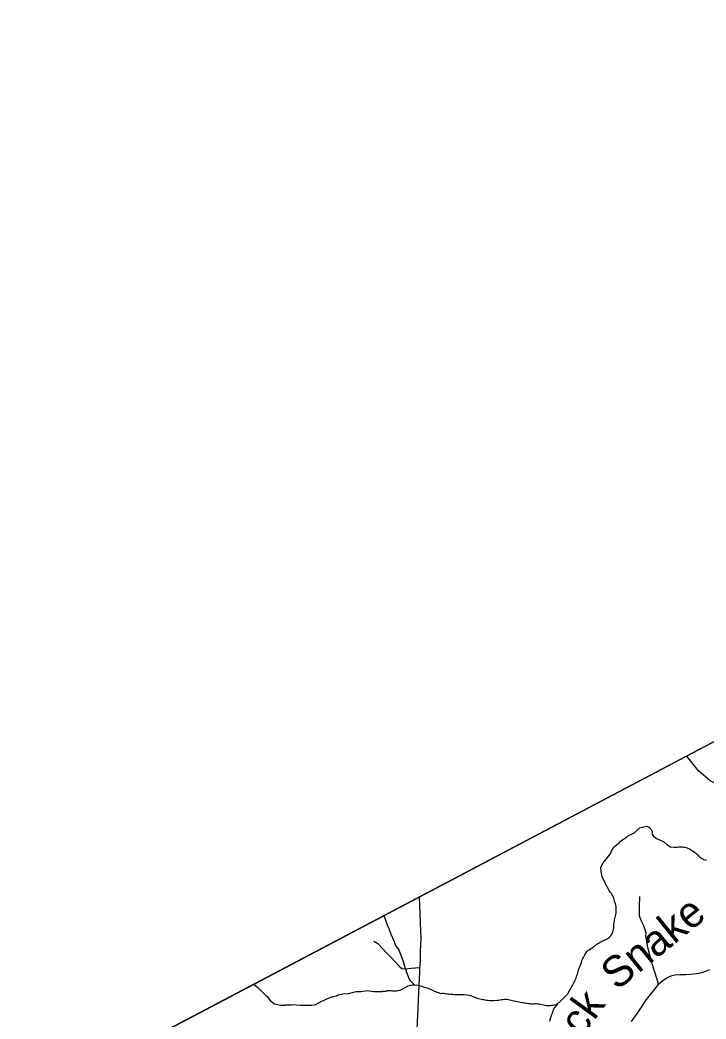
# Model space of a CAD drawing. Extents: x 1379448 to 1382868, y 593769 to 596827.
# Drawn here: x 1379496.1 to 1379823.8, y 595600.1 to 596077.5 of the extents above; entities that cross this region are included whole.
import ezdxf

# ---------------------------------------------------------------- set-up
doc = ezdxf.new("R2010")
doc.units = 0
for name, color, linetype in [('CTL Sheet Border CELL', 7, 'Continuous'), ('Old_Level_1', 7, 'Continuous'), ('Old_Level_11', 7, 'Continuous'), ('Old_Level_32', 7, 'Continuous'), ('Old_Level_35', 7, 'Continuous'), ('Old_Level_59', 7, 'Continuous'), ('Old_Level_62', 7, 'Continuous')]:
    doc.layers.add(name, color=color, linetype=linetype)

msp = doc.modelspace()

# ---------------------------------------------------------------- linework, layer by layer
at = {"layer": 'CTL Sheet Border CELL'}
msp.add_lwpolyline([(1381803.77, 596774.44), (1379496.12, 595557.87), (1380347.71, 593942.52), (1382655.37, 595159.09)], close=True, dxfattribs=at)
at = {"layer": 'Old_Level_1'}
msp.add_line((1379496.12, 595557.87), (1380161.32, 595908.56), dxfattribs=at)
at = {"layer": 'Old_Level_32'}
for points in [[(1379640.12, 595529.74), (1379643.82, 595532.3), (1379648.19, 595535.83), (1379652.41, 595539.5), (1379660.54, 595547.76), (1379671.85, 595560.64), (1379682.66, 595573), (1379683.63, 595574.88), (1379685.11, 595582.2), (1379685.85, 595595.01), (1379686.98, 595619.75), (1379687.08, 595622.03), (1379687.13, 595624.42), (1379687.25, 595625.44), (1379687.39, 595628.93), (1379687.49, 595632.65), (1379687.77, 595638.22), (1379687.48, 595646), (1379686.94, 595658.47)], [(1379788.24, 595598.85), (1379791.48, 595603.37), (1379795.35, 595609.37), (1379799.37, 595614.42), (1379801.15, 595616.52), (1379802, 595617.52), (1379803.38, 595618.6), (1379805.14, 595619.75), (1379806.29, 595620.36), (1379807.59, 595620.82), (1379808.94, 595621.18), (1379811.24, 595621.42), (1379814.24, 595621.45), (1379817.94, 595621.62), (1379820.53, 595621.96), (1379823.23, 595622.8), (1379825.56, 595623.75)]]:
    msp.add_lwpolyline(points, dxfattribs=at)
at = {"layer": 'Old_Level_35'}
for points in [[(1379801.15, 595616.52), (1379800.54, 595618.94), (1379797.95, 595626.98), (1379796.03, 595634.23), (1379795.14, 595639.73), (1379795.26, 595641.29), (1379794.12, 595644.59), (1379792.79, 595647.1), (1379792.02, 595649.45), (1379791.98, 595654.02), (1379792.26, 595658.65)], [(1379665.11, 595637.34), (1379666.98, 595636.12), (1379671.16, 595631.67), (1379673.47, 595629.57), (1379677.55, 595624.98), (1379678.51, 595624.29), (1379680.34, 595624.15), (1379683.01, 595624.34), (1379687.17, 595624.76)]]:
    msp.add_lwpolyline(points, dxfattribs=at)
at = {"layer": 'Old_Level_59'}
msp.add_lwpolyline([(1379865.99, 595712.11), (1379861.75, 595713.33), (1379854.56, 595711.67), (1379841.54, 595709.31), (1379836.17, 595709.93), (1379831.38, 595711.1), (1379825.8, 595713.98), (1379820.15, 595718.63), (1379814.61, 595725.77)], dxfattribs=at)
at = {"layer": 'Old_Level_62'}
for points in [[(1379775.12, 595666.31), (1379774.19, 595667.97), (1379773.68, 595670.58), (1379773.61, 595672.69), (1379774.69, 595674.65), (1379776.04, 595676.51), (1379777.98, 595678.8), (1379779.48, 595681.87), (1379779.91, 595682.44), (1379782.49, 595684.44), (1379782.92, 595685.02), (1379784.99, 595686.59), (1379785.85, 595687.02), (1379786.36, 595687.45), (1379789.75, 595689.23), (1379791.98, 595691.4), (1379795.58, 595692.23), (1379796.61, 595691.62), (1379797.63, 595690.68), (1379798.06, 595689.63), (1379798.13, 595688.4), (1379798.68, 595687.5), (1379799.84, 595686.63), (1379799.98, 595686.3), (1379802.13, 595685.59), (1379803.67, 595684.84), (1379805.17, 595683.44), (1379806.97, 595682.26)], [(1379813.14, 595682.11), (1379812.51, 595682.15), (1379811.87, 595682.17), (1379811.23, 595682.17), (1379810.59, 595682.16), (1379809.94, 595682.12), (1379809.3, 595682.02), (1379808.66, 595682.06), (1379806.97, 595682.26)], [(1379824.11, 595675.87), (1379823.46, 595676.03), (1379822.82, 595676.19), (1379822.21, 595676.42), (1379821.67, 595676.76), (1379821.18, 595677.19), (1379820.72, 595677.67), (1379820.26, 595678.16), (1379819.78, 595678.59), (1379819.27, 595678.97), (1379818.75, 595679.35), (1379818.23, 595679.71), (1379817.7, 595680.07), (1379817.16, 595680.42), (1379816.62, 595680.76), (1379816.09, 595681.09), (1379815.55, 595681.41), (1379814.99, 595681.71), (1379814.4, 595681.93), (1379813.77, 595682.04), (1379813.14, 595682.11)], [(1379752.69, 595607.15), (1379753.09, 595607.68), (1379753.61, 595608.06), (1379755.03, 595609.42), (1379756.88, 595611.23), (1379757.75, 595612.17), (1379758.1, 595612.73), (1379759.4, 595615.01), (1379759.73, 595615.58), (1379760.05, 595616.15), (1379760.36, 595616.73), (1379760.68, 595617.31), (1379760.97, 595617.89), (1379761.26, 595618.48), (1379761.52, 595619.08), (1379761.76, 595619.7), (1379761.98, 595620.32), (1379762.18, 595620.94), (1379762.36, 595621.57), (1379762.52, 595622.21), (1379762.68, 595622.85), (1379762.86, 595623.47), (1379763.09, 595624.09), (1379763.37, 595624.68), (1379764.26, 595627.15), (1379764.43, 595627.78), (1379764.68, 595628.39), (1379764.96, 595628.98), (1379765.26, 595629.56), (1379765.58, 595630.14), (1379765.9, 595630.71), (1379766.87, 595632.39), (1379767.39, 595632.78), (1379767.95, 595633.14), (1379770.08, 595634.62), (1379770.59, 595635.04), (1379771.11, 595635.43), (1379771.65, 595635.81), (1379772.19, 595636.18), (1379772.74, 595636.54), (1379773.31, 595636.87), (1379773.88, 595637.19), (1379774.47, 595637.48), (1379775.07, 595637.74), (1379775.68, 595638), (1379776.28, 595638.27), (1379776.86, 595638.57), (1379777.4, 595638.94), (1379777.87, 595639.41), (1379778.29, 595639.92), (1379778.69, 595640.45), (1379779.03, 595641), (1379779.3, 595641.59), (1379779.5, 595642.22), (1379779.65, 595642.87), (1379779.75, 595643.52), (1379779.8, 595644.17), (1379779.81, 595644.83), (1379779.84, 595645.49), (1379779.91, 595646.14), (1379780.03, 595646.78), (1379780.17, 595647.43), (1379780.33, 595648.07), (1379780.48, 595648.7), (1379780.63, 595649.34), (1379780.77, 595649.99), (1379780.88, 595650.63), (1379780.9, 595651.29), (1379780.97, 595653.21), (1379780.84, 595653.85), (1379780.68, 595654.49), (1379780.52, 595655.13), (1379780.17, 595656.4), (1379780, 595657.04), (1379779.81, 595657.67), (1379779.59, 595658.29), (1379779.33, 595658.88), (1379779.01, 595659.45), (1379778.63, 595660), (1379778.24, 595660.53), (1379777.49, 595661.57), (1379776.52, 595663.24), (1379776.23, 595663.83), (1379775.96, 595664.43), (1379775.12, 595666.31)], [(1379669.95, 595649.51), (1379671.58, 595645.15), (1379671.69, 595644.58), (1379672.44, 595643.08), (1379672.44, 595642.72), (1379673.15, 595641.29), (1379673.3, 595640.65), (1379674.87, 595637.15), (1379675.01, 595636.5), (1379675.8, 595634.75), (1379677.02, 595633.22), (1379679.09, 595627.64), (1379680.05, 595624.28), (1379680.52, 595623.35), (1379680.63, 595622.78), (1379681.92, 595619.63)], [(1379607.87, 595616.78), (1379609.61, 595615.28), (1379613.74, 595611.21), (1379614.05, 595611.06), (1379615.55, 595608.96), (1379617.69, 595607.35), (1379620.7, 595606.71), (1379622.84, 595606.7), (1379623.13, 595606.85), (1379625.63, 595606.85), (1379625.92, 595606.99), (1379630.04, 595606.64), (1379632.03, 595606.68), (1379635.45, 595606.76), (1379637.33, 595607.03), (1379640.6, 595608.75), (1379641.11, 595608.88), (1379642.31, 595609.63), (1379645.03, 595610.63), (1379645.38, 595610.63), (1379645.96, 595610.92), (1379647.25, 595611.21), (1379648.11, 595611.63), (1379650.11, 595611.92), (1379650.39, 595612.07), (1379653.11, 595612.35), (1379656.76, 595613.28), (1379659.06, 595613.28), (1379661.91, 595613.7), (1379665.17, 595613.28), (1379669.12, 595613.21)], [(1379684.7, 595616.28), (1379684.24, 595616.76), (1379683.71, 595617.2), (1379683.23, 595617.68), (1379682.8, 595618.2), (1379681.92, 595619.63)], [(1379684.7, 595616.28), (1379684.04, 595616.3), (1379683.39, 595616.24), (1379682.72, 595616.12), (1379682.05, 595615.96), (1379681.44, 595615.72), (1379680.84, 595615.44), (1379680.25, 595615.15), (1379679.66, 595614.85), (1379679.08, 595614.54), (1379678.5, 595614.24), (1379677.91, 595613.94), (1379676.69, 595613.52), (1379676.06, 595613.39), (1379675.42, 595613.35), (1379674.77, 595613.35), (1379674.13, 595613.43), (1379673.48, 595613.54), (1379672.84, 595613.61), (1379672.18, 595613.63), (1379671.55, 595613.51), (1379670.93, 595613.29), (1379669.12, 595613.21)], [(1379684.7, 595616.28), (1379685.37, 595616.36), (1379686.01, 595616.29), (1379686.64, 595616.13), (1379687.27, 595615.96), (1379687.9, 595615.77), (1379688.53, 595615.58), (1379689.16, 595615.39), (1379689.78, 595615.19), (1379690.41, 595614.98), (1379691.04, 595614.78), (1379691.66, 595614.57), (1379692.28, 595614.35), (1379692.89, 595614.1), (1379693.48, 595613.83), (1379694.03, 595613.47), (1379694.63, 595613.21), (1379695.25, 595612.99), (1379695.87, 595612.77), (1379697.1, 595612.35), (1379697.75, 595612.42), (1379698.41, 595612.38), (1379699.06, 595612.31), (1379699.72, 595612.25), (1379700.37, 595612.18), (1379701.02, 595612.11), (1379701.68, 595612.03), (1379702.33, 595611.97), (1379702.98, 595611.91), (1379703.64, 595611.86), (1379704.29, 595611.81), (1379704.94, 595611.8), (1379705.6, 595611.81), (1379706.26, 595611.84), (1379706.92, 595611.87), (1379707.57, 595611.87), (1379708.23, 595611.83), (1379710.83, 595611.44), (1379711.46, 595611.29), (1379712.08, 595611.08), (1379712.7, 595610.84), (1379713.3, 595610.58), (1379713.92, 595610.33), (1379714.53, 595610.12), (1379715.17, 595609.95), (1379715.8, 595609.79), (1379716.44, 595609.63), (1379717.09, 595609.49), (1379717.73, 595609.35), (1379718.38, 595609.23), (1379719.02, 595609.12), (1379719.67, 595609.03), (1379720.32, 595608.95), (1379720.97, 595608.91), (1379721.62, 595608.91), (1379722.28, 595608.96), (1379724.26, 595609.11), (1379724.91, 595609.16), (1379725.56, 595609.24), (1379726.18, 595609.42), (1379726.83, 595609.49), (1379727.49, 595609.53), (1379728.15, 595609.56), (1379728.8, 595609.55), (1379729.45, 595609.45), (1379730.09, 595609.28), (1379730.71, 595609.09), (1379731.35, 595608.91), (1379734.55, 595608.26), (1379735.19, 595608.14), (1379735.84, 595608.03), (1379736.48, 595607.93), (1379737.13, 595607.82), (1379737.78, 595607.72), (1379738.43, 595607.63), (1379739.08, 595607.54), (1379739.74, 595607.47), (1379740.39, 595607.41), (1379741.04, 595607.4), (1379741.7, 595607.42), (1379742.36, 595607.45), (1379743.02, 595607.45), (1379743.67, 595607.4), (1379744.32, 595607.3), (1379744.96, 595607.16), (1379745.6, 595607.01), (1379746.25, 595606.86), (1379746.89, 595606.72), (1379747.53, 595606.59), (1379748.17, 595606.51), (1379748.83, 595606.51), (1379749.49, 595606.57), (1379750.14, 595606.66), (1379750.79, 595606.77), (1379751.43, 595606.9), (1379752.69, 595607.15)], [(1379752.69, 595607.15), (1379751.84, 595606.14), (1379751.44, 595605.62), (1379751.08, 595605.08), (1379750.82, 595604.47), (1379750.6, 595603.85), (1379749.55, 595600.74), (1379749.06, 595598.91)]]:
    msp.add_lwpolyline(points, dxfattribs=at)

# ---------------------------------------------------------------- texts
at = {"layer": 'Old_Level_11'}
for s, rotation, p in [('Snake', 39.052, (1379781.23, 595613.42)), ('Black', 53.9661, (1379747.78, 595568.04))]:
    msp.add_text(s, height=14.764, rotation=rotation, dxfattribs=at).set_placement(p)

doc.saveas('drawing.dxf')
